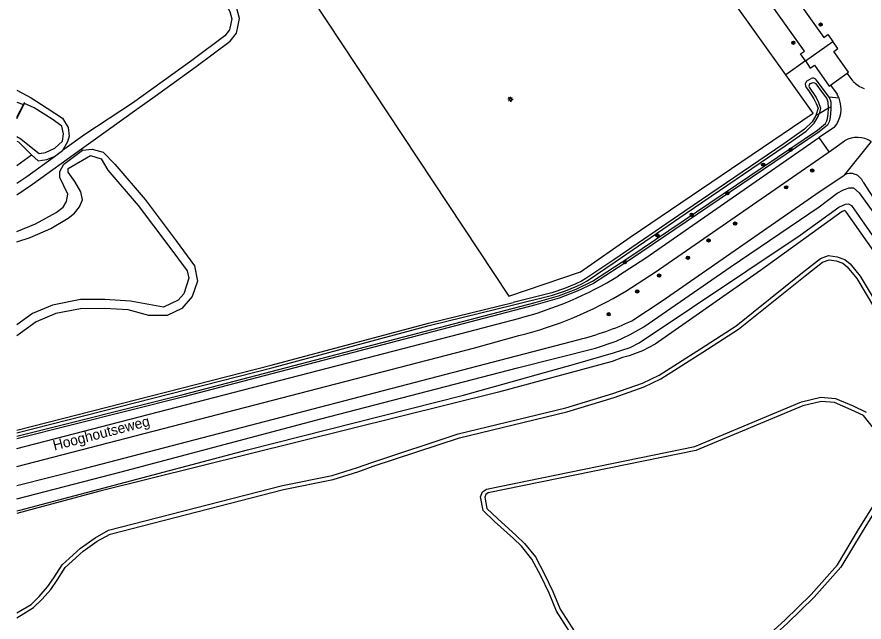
# Model space of a CAD drawing. Extents: x 141000 to 143000, y 400580 to 403500.
# Drawn here: x 141000 to 141206, y 402525 to 402672.1 of the extents above; entities that cross this region are included whole.
import ezdxf

# ---------------------------------------------------------------- set-up
doc = ezdxf.new("R2010")
doc.units = 0
for name, color, linetype in [('gg-afsc-erfafscheiding', 7, 'Continuous'), ('gg-afsc-hekwerk', 7, 'Continuous'), ('gg-anno-openbare ruimte label', 7, 'Continuous'), ('gg-knt-bovenkant onderkant talud', 7, 'Continuous'), ('gg-knt-verharding', 7, 'Continuous'), ('gg-kntw-bovenkant insteek waterloop', 7, 'Continuous'), ('gg-kntw-waterlijn', 7, 'Continuous'), ('gg-kwrk-stuw', 7, 'Continuous'), ('gt-grn-groengrens', 7, 'Continuous'), ('gt-grn-vlakafsluiter', 7, 'Continuous'), ('gt-symb-boom', 7, 'Continuous'), ('gt-symb-lichtmast', 7, 'Continuous')]:
    doc.layers.add(name, color=color, linetype=linetype)

# ---------------------------------------------------------------- blocks, each defined once
blk = doc.blocks.new('gt0-BOOM')
at = {"layer": 'gt-symb-boom'}
for radius in [0.4, 0.2]:
    blk.add_circle((0, 0), radius, dxfattribs=at)
blk = doc.blocks.new('gt0-LMAST')
at = {"layer": 'gt-symb-lichtmast'}
for p, q in [((-0.18, 0.17), (-0.45, 0.44)), ((-0.01, 0.25), (-0.01, 0.62)), ((0.17, 0.17), (0.44, 0.44)), ((-0.26, 0), (-0.63, 0)), ((-0.18, -0.18), (-0.45, -0.45)), ((-0.01, -0.25), (-0.01, -0.63)), ((0.44, -0.45), (0.17, -0.18)), ((0.24, 0), (0.62, 0))]:
    blk.add_line(p, q, dxfattribs=at)
blk.add_circle((-0.01, 0), 0.25, dxfattribs=at)

msp = doc.modelspace()

# ---------------------------------------------------------------- linework, layer by layer
at = {"layer": 'gg-afsc-erfafscheiding'}
msp.add_line((141069.96, 402679.26), (141119.65, 402604.15), dxfattribs=at)
at = {"layer": 'gg-afsc-hekwerk'}
for p, q in [((141186.97, 402657.95), (141155.99, 402701.45)), ((141191.75, 402661.36), (141198.44, 402666.08)), ((141191.75, 402661.36), (141186.97, 402657.95))]:
    msp.add_line(p, q, dxfattribs=at)
for points in [[(141119.65, 402604.15), (141137.06, 402610.09), (141149.09, 402618.52), (141193.6, 402648.65), (141186.97, 402657.95)], [(141119.65, 402604.15), (141137.06, 402610.09), (141149.09, 402618.52), (141193.6, 402648.65)]]:
    msp.add_lwpolyline(points, dxfattribs=at)
at = {"layer": 'gg-knt-bovenkant onderkant talud'}
msp.add_line((141000, 402635.92), (141003.57, 402638.52), dxfattribs=at)
at = {"layer": 'gg-knt-verharding'}
for p, q in [((141197.85, 402655.48), (141201.91, 402658.42)), ((141203.36, 402656.41), (141201.91, 402658.42)), ((141197.85, 402655.48), (141199.43, 402653.29)), ((141198.79, 402645.27), (141195.12, 402642.72)), ((141197.52, 402639.28), (141195.12, 402642.72)), ((141009.14, 402638.17), (141011.11, 402639.6))]:
    msp.add_line(p, q, dxfattribs=at)
for points in [[(141032.52, 402700.59), (141046.83, 402680.58), (141050.53, 402675.49), (141051.78, 402673.41), (141052.27, 402671.62), (141052.05, 402670.43), (141051.7, 402668.92), (141050.58, 402667.46), (141042.53, 402661.46), (141028.12, 402651.12)], [(141191.75, 402661.36), (141190.58, 402663.11), (141191.51, 402663.73), (141164.02, 402702.3)], [(141173.49, 402698.9), (141196.21, 402667.07), (141197.22, 402667.79), (141198.44, 402666.08)], [(141033.63, 402652.84), (141043.59, 402660.01), (141051.85, 402666.16), (141053.37, 402668.13), (141053.82, 402670.07), (141054.11, 402671.7), (141053.45, 402674.13), (141052.04, 402676.48)], [(141201.91, 402658.42), (141202.21, 402658.64), (141198.64, 402663.64), (141199.66, 402664.37), (141198.44, 402666.08)], [(141191.75, 402661.36), (141192.92, 402659.61), (141193.95, 402660.32), (141197.56, 402655.27), (141197.85, 402655.48)], [(141028.12, 402651.12), (141016.48, 402643.49), (141011.11, 402639.6)], [(141015.69, 402639.97), (141017.96, 402641.59), (141029.15, 402649.65), (141033.63, 402652.84)], [(141195.12, 402642.72), (141194.91, 402642.57), (141152.91, 402613.38), (141146.29, 402609.09)], [(141197.52, 402639.28), (141198.63, 402640.05), (141201.29, 402641.96)], [(141000, 402628.82), (141003.77, 402631.43), (141015.69, 402639.97)], [(141148.05, 402605.41), (141155.17, 402610.01), (141197.3, 402639.13), (141197.52, 402639.28)], [(141000, 402631.67), (141002.39, 402633.28), (141009.14, 402638.17)], [(141000, 402567.13), (141109.9, 402595.6), (141121.95, 402598.78)], [(141000, 402562.8), (141111.01, 402591.56), (141122.02, 402594.58)]]:
    msp.add_lwpolyline(points, dxfattribs=at)
for centre, radius, start, end in [((141208.83, 402661.7), 7.61, 224.0966, 248.2539), ((141193.55, 402649.67), 6.9, 22.2717, 31.5894), ((141193.63, 402649.71), 6.81, 319.2713, 22.1935), ((141204.34, 402636.41), 6.34, 57.4674, 118.7911), ((141099.24, 402686.28), 90.4, 284.5509, 301.3613), ((141098.67, 402687.42), 95.73, 284.1173, 301.0552)]:
    msp.add_arc(centre, radius, start, end, dxfattribs=at)
at = {"layer": 'gg-kntw-bovenkant insteek waterloop'}
msp.add_line((141192.04, 402656.46), (141193.12, 402657.1), dxfattribs=at)
for points in [[(141197.52, 402652.57), (141196.35, 402654.07), (141194.4, 402656.78)], [(141000, 402654.26), (141003.46, 402652.4), (141007.39, 402649.88), (141011.1, 402647.42), (141012.49, 402645.2), (141012.73, 402643.11), (141012.33, 402641.73), (141011.11, 402639.6)], [(141191.95, 402654.93), (141192.46, 402654.21), (141193.82, 402652.15), (141194.4, 402651.05), (141194.82, 402649.89), (141194.3, 402648.09)], [(141197.52, 402652.57), (141197.9, 402651.41), (141197.92, 402650.22)], [(141197.92, 402650.22), (141197.93, 402649.81), (141197.85, 402648.41), (141197.72, 402647.23), (141197.52, 402646.54), (141197.11, 402645.79), (141195.06, 402644.09), (141149.17, 402613.11), (141140.23, 402607.27), (141136.27, 402605.36), (141131.88, 402603.72), (141126.16, 402602.05), (141040.6, 402579.7), (141000, 402569.5)], [(141194.3, 402648.09), (141193.41, 402646.59), (141191.53, 402644.74), (141186.48, 402641.22), (141162.4, 402624.86), (141145.13, 402613.01), (141138.32, 402608.44), (141137.27, 402607.81), (141135.89, 402607.16), (141133.18, 402606.04), (141130.11, 402604.99), (141120.64, 402602.66)], [(141000, 402641.87), (141000.35, 402641.68), (141003.57, 402638.52)], [(141015.93, 402639.64), (141018.26, 402639.92), (141020.95, 402639.22), (141023.79, 402636.26), (141031.17, 402627.67), (141038.73, 402617.66), (141043.15, 402611.58), (141043.87, 402607.85), (141042.63, 402604.1), (141040.12, 402601.2), (141036.56, 402599.51), (141032.08, 402599.48), (141027.02, 402600.82), (141021.41, 402601.18), (141015.43, 402601.14), (141009.49, 402599.93), (141004.64, 402597.96), (141000, 402594.51)], [(141000, 402619.93), (141004.51, 402621.8), (141009.53, 402624.53), (141011.22, 402625.79), (141012.03, 402627.2), (141012.34, 402628.98), (141010.44, 402633.06), (141010.42, 402634.45), (141011.37, 402636.3), (141015.93, 402639.64)], [(141003.57, 402638.52), (141005.14, 402637.11), (141007.27, 402637.42), (141009.14, 402638.17)], [(141149.55, 402598.2), (141156.89, 402603.05), (141194.26, 402628.99), (141201.17, 402633.63)], [(141205.77, 402631.92), (141209.78, 402625.77), (141217.57, 402614.31), (141287.71, 402518.22), (141318.51, 402476.54), (141324.85, 402466.58), (141326.35, 402462.55), (141326.01, 402460.56), (141320.75, 402454.95), (141320.27, 402454.53)], [(141228.75, 402586.19), (141201.62, 402624.67), (141201.3, 402624.97), (141200.66, 402624.76), (141180.81, 402610.44), (141155.19, 402592.49), (141152.15, 402590.86), (141148.91, 402589.65), (141147.23, 402589.24), (141144.78, 402588.33), (141117.1, 402580.85), (141020.19, 402556.75), (141000, 402551.32)], [(141000, 402527.18), (141003.43, 402529.26), (141005.38, 402531.2), (141007.46, 402533.48), (141008.98, 402535.69), (141010.96, 402538.88), (141015.48, 402542.93), (141019.02, 402545.43), (141022.28, 402547.27), (141064.61, 402558.12), (141076.68, 402560.59), (141082.8, 402562.54), (141086.33, 402563.77), (141107.33, 402570.71), (141133.49, 402577.07), (141144.94, 402580.51), (141152.14, 402583.06), (141156.14, 402584.94), (141166.25, 402591.37), (141174.93, 402596.93), (141191.04, 402609.95), (141195.45, 402613.35), (141197.38, 402614.04), (141199.47, 402613.77), (141201.3, 402613.09), (141202.63, 402612.06), (141205.07, 402609.08), (141211.68, 402597.91)], [(141000, 402571.6), (141061.8, 402587.37), (141100.08, 402597.59), (141120.64, 402602.66)], [(141000, 402558.14), (141016.68, 402562.38), (141136.71, 402593.64)], [(141208.34, 402572.05), (141205.86, 402575.19), (141202.91, 402576.58), (141198.84, 402578.3), (141195.59, 402578.61), (141191.14, 402577.51), (141165.13, 402566.7), (141114.57, 402556.35), (141114.02, 402555.95), (141113.77, 402555.28), (141114.31, 402552.58), (141116.86, 402550.15), (141121.4, 402546.01), (141123.44, 402544.07), (141126.07, 402540.8), (141128.26, 402536.61), (141130.32, 402532.37), (141132.07, 402528.07), (141135.73, 402522.38)], [(141160.49, 402508.33), (141166.35, 402511.2), (141173.32, 402514.36), (141178.76, 402518.17), (141186.71, 402525.43), (141193.18, 402531.67), (141199.58, 402538.89), (141204.68, 402547.42), (141211.31, 402558.09)]]:
    msp.add_lwpolyline(points, dxfattribs=at)
for centre, radius, start, end in [((141193.53, 402656.03), 1.15, 41.1815, 110.8727), ((141192.95, 402655.63), 1.23, 137.7096, 214.9797), ((141202.69, 402630.68), 3.32, 21.985, 117.2665), ((141118.93, 402664.06), 72.63, 284.1711, 294.9335)]:
    msp.add_arc(centre, radius, start, end, dxfattribs=at)
at = {"layer": 'gg-kntw-waterlijn'}
msp.add_line((141000, 402651.34), (141001.58, 402650.79), dxfattribs=at)
for points in [[(141197.34, 402649.88), (141197.3, 402651.31), (141196.98, 402652.29), (141195.87, 402653.71), (141194.35, 402655.83)], [(141192.63, 402655.01), (141194.33, 402652.46), (141194.95, 402651.29), (141195.45, 402649.91), (141195.05, 402648.53)], [(141000, 402643), (141000.92, 402642.41), (141003.46, 402640.42), (141005.37, 402638.86), (141006.93, 402639.13), (141009.23, 402640.15), (141011.1, 402641.84), (141011.35, 402643.68), (141010.93, 402645.51), (141008.54, 402647.18), (141004.17, 402649.98), (141001.86, 402650.98)], [(141000, 402570.12), (141040.45, 402580.29), (141126, 402602.62), (141131.69, 402604.29), (141136.03, 402605.91), (141139.93, 402607.79), (141148.84, 402613.61), (141194.7, 402644.57), (141196.64, 402646.18), (141196.96, 402646.77), (141197.13, 402647.35), (141197.25, 402648.46), (141197.34, 402649.88)], [(141000, 402570.98), (141061.95, 402586.79), (141100.23, 402597.01), (141120.78, 402602.08), (141130.28, 402604.42), (141133.4, 402605.48), (141136.13, 402606.61), (141137.55, 402607.28), (141138.64, 402607.94), (141145.46, 402612.51), (141162.74, 402624.36), (141186.82, 402640.73), (141191.92, 402644.28), (141193.89, 402646.22), (141194.86, 402647.85), (141195.05, 402648.53)], [(141000, 402617.39), (141003.2, 402618.42), (141008.21, 402620.66), (141012.45, 402623.15), (141013.97, 402624.34), (141015.21, 402625.92), (141015.92, 402627.58), (141015.5, 402629.53), (141014.1, 402632.06), (141012.49, 402634.36), (141012.48, 402635.25), (141017.85, 402638.38), (141020.52, 402637.58), (141022.13, 402634.83), (141029.51, 402626.24), (141036.96, 402616.37), (141041.38, 402610.3), (141041.79, 402608.54), (141040.55, 402604.78), (141039.19, 402603.18), (141035.62, 402601.49), (141027.58, 402602.93), (141021.4, 402603.37), (141015.42, 402603.33), (141008.67, 402601.96), (141003.82, 402599.99), (141000, 402597.2)], [(141000, 402554.95), (141025.31, 402561.46), (141073.92, 402574.34), (141121.71, 402586.77), (141140.7, 402591.5), (141145.69, 402593.23), (141149.1, 402594.85), (141152.45, 402596.73), (141173.48, 402611.21), (141195.1, 402625.91), (141199.49, 402629.23), (141200.98, 402630.05), (141202.42, 402630.54), (141203.47, 402630.5), (141204.81, 402629.28), (141216.55, 402613.05)], [(141000, 402552.02), (141000.71, 402552.19), (141056.08, 402566.83), (141108.59, 402580.09), (141135.86, 402587.71), (141145.06, 402590.42), (141149.14, 402591.73), (141151.29, 402592.83), (141190.45, 402619.03), (141199.86, 402625.85), (141201.52, 402626.58), (141202.24, 402626.66), (141202.98, 402626.22), (141228.7, 402589.24)], [(141000, 402526.01), (141004.05, 402528.47), (141006.1, 402530.5), (141008.25, 402532.86), (141009.82, 402535.15), (141011.74, 402538.23), (141016.1, 402542.15), (141019.55, 402544.59), (141022.66, 402546.33), (141064.84, 402557.14), (141076.93, 402559.62), (141083.12, 402561.59), (141086.65, 402562.83), (141107.61, 402569.74), (141133.75, 402576.1), (141145.25, 402579.56), (141152.52, 402582.14), (141156.62, 402584.06), (141166.79, 402590.53), (141175.51, 402596.12), (141191.66, 402609.16), (141195.94, 402612.46), (141197.49, 402613.02), (141199.23, 402612.79), (141200.81, 402612.2), (141201.93, 402611.34), (141204.25, 402608.51), (141210.79, 402597.45)], [(141149.08, 402507.32), (141146.74, 402509.05), (141144.81, 402510.89), (141138.53, 402517.72), (141134.93, 402521.77), (141131.18, 402527.61), (141129.4, 402531.97), (141127.37, 402536.16), (141125.23, 402540.25), (141122.7, 402543.39), (141120.72, 402545.28), (141116.17, 402549.42), (141113.39, 402552.08), (141112.74, 402555.36), (141113.18, 402556.58), (141114.16, 402557.28), (141164.84, 402567.66), (141190.83, 402578.46), (141195.52, 402579.62), (141199.09, 402579.28), (141203.32, 402577.49), (141206.49, 402575.99)], [(141212.2, 402557.63), (141205.54, 402546.9), (141200.39, 402538.3), (141193.9, 402530.97), (141187.39, 402524.7), (141179.39, 402517.39), (141173.82, 402513.49), (141166.77, 402510.29), (141160.82, 402507.38), (141156.7, 402506.5), (141153.81, 402506.59), (141150.98, 402506.74), (141149.08, 402507.32)]]:
    msp.add_lwpolyline(points, dxfattribs=at)
for centre, radius, start, end in [((141193.43, 402655.18), 0.821, 126.0588, 191.9123), ((141193.64, 402654.62), 1.4, 59.5555, 119.4609)]:
    msp.add_arc(centre, radius, start, end, dxfattribs=at)
at = {"layer": 'gg-kwrk-stuw'}
for p, q in [((141000, 402647.36), (141001.86, 402650.98)), ((141000, 402647.71), (141001.58, 402650.79))]:
    msp.add_line(p, q, dxfattribs=at)
msp.add_lwpolyline([(141001.86, 402650.98), (141001.93, 402651.12), (141001.79, 402651.2), (141001.58, 402650.79)], dxfattribs=at)
at = {"layer": 'gt-grn-groengrens'}
for p, q in [((141199.94, 402652.29), (141197.52, 402652.57)), ((141207.75, 402641.75), (141201.17, 402633.63))]:
    msp.add_line(p, q, dxfattribs=at)
at = {"layer": 'gt-grn-vlakafsluiter'}
for p, q in [((141197.34, 402649.88), (141195.05, 402648.53)), ((141197.34, 402649.88), (141197.92, 402650.22)), ((141195.05, 402648.53), (141194.3, 402648.09)), ((141015.93, 402639.64), (141015.69, 402639.97))]:
    msp.add_line(p, q, dxfattribs=at)

# ---------------------------------------------------------------- block references
at = {"layer": 'gt-symb-boom'}
for p in [(141195.45, 402670.19), (141188.81, 402665.78), (141188.15, 402639.77), (141181.46, 402636.15), (141193.42, 402634.72), (141187.05, 402630.64), (141172.77, 402629.19), (141164.08, 402623.98), (141174.64, 402621.84), (141155.75, 402618.96), (141168.18, 402617.73), (141163.16, 402613.51), (141147.87, 402612.47), (141156.17, 402609.2), (141150.85, 402605.33), (141143.9, 402599.78)]:
    msp.add_blockref('gt0-BOOM', p, dxfattribs=at)
at = {"layer": 'gt-symb-lichtmast'}
msp.add_blockref('gt0-LMAST', (141120.02, 402652.05), dxfattribs=at)

# ---------------------------------------------------------------- texts
at = {"layer": 'gg-anno-openbare ruimte label'}
msp.add_text('Hooghoutseweg', height=2.5, rotation=14.5, dxfattribs=at).set_placement((141009.11, 402566.65))

doc.saveas('drawing.dxf')
